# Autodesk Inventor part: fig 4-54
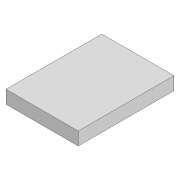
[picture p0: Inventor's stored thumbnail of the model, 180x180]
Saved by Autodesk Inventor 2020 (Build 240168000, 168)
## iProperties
Created: 2019-07
Part Number: fig 4-54
Material: Generic
Document SubType Name: Modeling
Designer: LENOVO-CADCIM
Density: 1 g/cm^3
Appearance: Default
Author: LENOVO-CADCIM
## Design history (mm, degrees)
sketch "Sketch1"
  geometry: L1 (-13.871, 18.394)-(13.871, 18.394); L2 (13.871, 18.394)-(13.871, -18.394); L3 (13.871, -18.394)-(-13.871, -18.394); L4 (-13.871, -18.394)-(-13.871, 18.394); L5 (-13.871, 18.394)-(13.871, -18.394); L6 (13.871, 18.394)-(-13.871, -18.394); 1 further point
  constraints: 12 end point, 2 midpoint, 2 parallel, 1 horizontal, 1 perpendicular
extrude "Extrusion1" new body sketch "Sketch1" distance "d0" = 5; taper "d1" = 0 deg
body "Solid1"
